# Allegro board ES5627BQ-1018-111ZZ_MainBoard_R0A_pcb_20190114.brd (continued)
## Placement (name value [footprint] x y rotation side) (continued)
CB740  1uF/16V  [CC0402_22X22_8OCT]  25.22 99.67 0 bottom
CB741  1uF/16V  [CC0402_22X22_8OCT]  27.28 99.67 180 bottom
CB742  1uF/16V  [CC0402_22X22_8OCT]  29.21 99.67 0 bottom
CB743  1uF/16V  [CC0402_22X22_8OCT]  31.22 99.67 180 bottom
CB744  1uF/16V  [CC0402_22X22_8OCT]  36.17 99.67 0 bottom
CB745  1uF/16V  [CC0402_22X22_8OCT]  39.17 99.67 180 bottom
CB746  1uF/16V  [CC0402_22X22_8OCT]  41.15 99.67 0 bottom
CB747  1uF/16V  [CC0402_22X22_8OCT]  43.18 99.67 180 bottom
CB748  1uF/16V  [CC0402_22X22_8OCT]  45.14 99.67 0 bottom
CB749  1uF/16V  [CC0402_22X22_8OCT]  47.12 99.67 180 bottom
CB750  1uF/16V  [CC0402_22X22_8OCT]  51.13 99.67 180 bottom
CB751  1uF/16V  [CC0402_22X22_8OCT]  55.12 99.67 180 bottom
CB752  1uF/16V  [CC0402_22X22_8OCT]  49.18 99.63 0 bottom
CB756  1uF/16V  [CC0402_22X22_8OCT]  23.75 99.16 90 bottom
CB757  0.1uF/16V  [CC0402]  111.85 99.16 270 bottom
CB758  1uF/16V  [CC0402_22X22_8OCT]  56.71 99.13 90 bottom
CB759  10uF/16V  [CC0805]  196.39 102.56 90 top
CB765  1uF/16V  [CC0402_22X22_8OCT]  21.21 98.66 0 bottom
CB766  1uF/16V  [CC0402_22X22_8OCT]  53.21 98.63 0 bottom
CB767  1uF/16V  [CC0402_22X22_8OCT]  27.18 97.64 0 bottom
CB768  1uF/16V  [CC0402_22X22_8OCT]  31.17 97.64 0 bottom
CB769  1uF/16V  [CC0402_22X22_8OCT]  35.18 97.64 0 bottom
CB770  1uF/16V  [CC0402_22X22_8OCT]  39.17 97.64 0 bottom
CB771  1uF/16V  [CC0402_22X22_8OCT]  43.21 97.64 0 bottom
CB772  1uF/16V  [CC0402_22X22_8OCT]  47.22 97.64 0 bottom
CB773  1uF/16V  [CC0402_22X22_8OCT]  51.21 97.64 0 bottom
CB774  1uF/16V  [CC0402_22X22_8OCT]  55.25 97.64 0 bottom
CB775  1uF/16V  [CC0402_22X22_8OCT]  23.75 97.15 90 bottom
CB776  1nF  [CC0402]  113.5 97.13 180 bottom
CB783  470uF/2V/4A  [CAP_6D4_2SP_4D3W7D3L2D1H]  82.39 95.86 0 bottom
CB786  100uF/6.3V  [CC1206]  154.78 84.94 270 top
CB787  100uF/6.3V  [CC1206]  163.73 93.11 0 bottom
CB788  100uF/6.3V  [CC1206]  166.01 93.11 0 bottom
CB789  100uF/6.3V  [CC1206]  168.42 93.11 0 bottom
CB790  0.1uF  [CC0603]  145.73 99.55 270 bottom
CB793  100uF/6.3V  [CC1206]  154.73 87.4 90 bottom
CB796  0.1uF/16V  [CC0402]  180.13 68.74 0 top
CB797  22uF, 16V  [CC1206]  237.63 70.05 180 bottom
CB799  0.1uF/16V  [CC0402]  35.33 68.74 0 top
CB800  0.1uF/16V  [CC0402]  41.36 68.87 180 bottom
CB801  0.1uF/16V  [CC0402]  60.41 68.74 0 top
CB806  0.1uF/16V  [CC0402]  72.92 68.74 180 bottom
CB807  0.1uF/16V  [CC0402]  72.92 68.74 0 top
CB808  0.1uF/16V  [CC0402]  85.44 68.68 180 bottom
CB809  0.1uF/16V  [CC0402]  85.44 68.68 0 top
CB810  0.1uF/16V  [CC0402]  109.77 68.87 180 bottom
CB811  0.1uF/16V  [CC0402]  116.25 68.74 180 bottom
CB812  0.1uF/16V  [CC0402]  128.82 68.74 0 top
CB813  0.1uF/16V  [CC0402]  122.35 68.87 0 top
CB814  0.1uF/16V  [CC0402]  136.96 68.62 180 bottom
CB815  0.1uF/16V  [CC0402]  136.96 68.62 0 top
CB816  0.1uF/16V  [CC0402]  154.98 68.74 0 top
CB817  0.1uF/16V  [CC0402]  154.98 68.74 180 bottom
CB818  0.1uF/16V  [CC0402]  161.02 68.87 0 top
CB819  0.1uF/16V  [CC0402]  167.49 68.74 180 bottom
CB820  0.1uF/16V  [CC0402]  173.65 68.87 180 bottom
CB821  0.1uF/16V  [CC0402]  186.29 68.87 0 top
CB822  0.1uF/16V  [CC0402]  192.77 68.74 0 top
CB827  0.1uF/16V  [CC0402]  35.33 68.74 180 bottom
CB828  0.1uF/16V  [CC0402]  41.36 68.87 0 top
CB829  0.1uF/16V  [CC0402]  60.41 68.74 180 bottom
CB832  22uF/6.3V  [CC0603]  67.46 66.4 270 top
CB833  22uF/6.3V  [CC0603]  71.78 66.39 270 bottom
CB834  22uF/6.3V  [CC0603]  79.97 66.39 270 top
CB835  22uF/6.3V  [CC0603]  84.23 66.4 270 bottom
CB836  22uF/6.3V  [CC0603]  110.79 66.39 270 top
CB837  22uF/6.3V  [CC0603]  115.11 66.39 270 bottom
CB838  22uF/6.3V  [CC0603]  123.36 66.39 270 top
CB839  22uF/6.3V  [CC0603]  127.68 66.39 270 bottom
CB840  22uF/6.3V  [CC0603]  131.63 66.27 270 top
CB841  22uF/6.3V  [CC0603]  135.82 66.27 270 bottom
CB842  22uF/6.3V  [CC0603]  149.52 66.4 270 top
CB843  22uF/6.3V  [CC0603]  153.84 66.39 270 bottom
CB844  22uF/6.3V  [CC0603]  161.91 66.4 270 top
CB845  22uF/6.3V  [CC0603]  166.35 66.4 270 bottom
CB846  22uF/6.3V  [CC0603]  174.67 66.39 270 top
CB847  22uF/6.3V  [CC0603]  178.99 66.39 270 bottom
CB848  22uF/6.3V  [CC0603]  187.31 66.39 270 top
CB849  22uF/6.3V  [CC0603]  191.62 66.39 270 bottom
CB852  22uF/6.3V  [CC0603]  29.87 66.39 270 top
CB853  22uF/6.3V  [CC0603]  34.19 66.39 270 bottom
CB854  22uF/6.3V  [CC0603]  42.32 66.4 270 top
CB855  22uF/6.3V  [CC0603]  46.7 66.39 90 top
CB856  22uF/6.3V  [CC0603]  59.27 66.39 90 top
CB857  22uF/6.3V  [CC0603]  54.95 66.4 270 top
CB858  0.1uF/16V  [CC0402]  29.36 65.12 270 top
CB859  0.1uF/16V  [CC0402]  34.7 65.12 270 bottom
CB860  0.1uF/16V  [CC0402]  41.93 65.06 270 top
CB861  0.1uF/16V  [CC0402]  47.2 65.12 90 top
CB862  0.1uF/16V  [CC0402]  59.78 65.12 90 top
CB863  0.1uF/16V  [CC0402]  54.51 65.13 270 top
CB864  0.1uF/16V  [CC0402]  67.08 65.13 270 top
CB865  0.1uF/16V  [CC0402]  72.29 65.12 270 bottom
CB866  0.1uF/16V  [CC0402]  79.46 65.12 270 top
CB867  0.1uF/16V  [CC0402]  84.73 65.13 270 bottom
CB868  0.1uF/16V  [CC0402]  110.28 65.12 270 top
CB869  0.1uF/16V  [CC0402]  115.61 65.12 270 bottom
CB870  0.1uF/16V  [CC0402]  122.85 65.12 270 top
CB871  0.1uF/16V  [CC0402]  128.19 65.12 270 bottom
CB872  0.1uF/16V  [CC0402]  130.99 65 270 top
CB873  0.1uF/16V  [CC0402]  136.33 65 270 bottom
CB874  0.1uF/16V  [CC0402]  149.02 65.13 270 top
CB875  0.1uF/16V  [CC0402]  154.35 65.12 270 bottom
CB876  0.1uF/16V  [CC0402]  161.52 65.13 270 top
CB877  0.1uF/16V  [CC0402]  166.83 65.12 270 bottom
CB878  0.1uF/16V  [CC0402]  174.16 65.12 270 top
CB879  0.1uF/16V  [CC0402]  179.5 65.12 270 bottom
CB880  0.1uF/16V  [CC0402]  186.8 65.12 270 top
CB881  0.1uF/16V  [CC0402]  192.13 65.12 270 bottom
CB883  0.1uF/16V  [CC0402]  179.59 21.46 90 bottom
CB892  10uF/6.3V  [CC0603]  220.07 112.27 90 top
CB893  @1nF  [CC0402]  239.18 80.17 90 top
CB894  @1nF  [CC0402]  241.09 80.17 270 top
CB895  @1nF  [CC0402]  242.99 80.17 90 top
CB896  @1nF  [CC0402]  244.9 80.17 90 top
CB898  10uF/6.3V  [CC0603]  220.08 109.34 270 top
CB899  0.1uF/16V  [CC0402]  211.3 75.42 90 top
CB900  0.1uF/16V  [CC0402]  199.55 74.65 90 top
CB901  0.1uF/16V  [CC0402]  207.43 75.42 90 top
CB902  0.1uF/16V  [CC0402]  211.3 75.42 270 bottom
CB903  0.1uF/16V  [CC0402]  240.12 155.93 270 top
CB904  22uF/6.3V  [CC0805]  199.74 76.3 90 top
CB905  22uF/6.3V  [CC0805]  211.81 76.95 270 bottom
CB906  22uF/6.3V  [CC0805]  208 76.95 90 top
CB907  22uF/6.3V  [CC0805]  211.81 76.95 90 top
CB908  0.1uF/16V  [CC0402]  216.25 75.28 90 top
CB909  0.1uF/16V  [CC0402]  204.44 75.35 270 top
CB910  22uF/6.3V  [CC0805]  204.05 76.93 270 top
CB911  22uF/6.3V  [CC0805]  215.61 76.93 90 top
CB912  @100pF/100V  [CC0402]  244.44 153.77 0 top
CB913  @100pF/100V  [CC0402]  244.44 155.67 180 top
CB914  0.1uF/16V  [CC0402]  244.06 157.71 90 top
CB915  @100pF/100V  [CC0402]  247.49 152.5 180 top
CB916  @100pF/100V  [CC0402]  247.49 150.59 0 top
CB917  22uF/6.3V  [CC0805]  206.8 84.25 180 top
CB918  22uF/6.3V  [CC0805]  213.63 84.27 180 top
CB919  0.1uF/16V  [CC0402]  202.34 79.35 0 top
CB920  0.1uF/16V  [CC0402]  215.36 83.16 180 top
CB921  0.1uF/16V  [CC0402]  242.15 157.71 90 top
CB922  0.1uF/16V  [CC0402]  246.98 157.71 270 top
CB923  0.1uF/16V  [CC0402]  242.92 152.37 90 top
CB926  @100pF/100V  [CC0402]  256.94 35.18 0 bottom
CB927  @100pF/100V  [CC0402]  260.79 35.18 0 bottom
CB928  @100pF/100V  [CC0402]  256.94 35.18 180 top
CB929  @100pF/100V  [CC0402]  260.79 35.18 180 top
CB930  @100pF/100V  [CC0402]  258.74 35.18 0 bottom
CB931  @100pF/100V  [CC0402]  258.74 35.18 180 top
CB937  0.1uF/16V  [CC0402]  249.65 67.79 180 bottom
CB938  @0.1uF/16V  [CC0402]  88.89 29.47 270 bottom
CB942  0.1uF  [CC0402]  243.36 8.93 180 bottom
CB949  0.1uF/16V  [CC0402]  136.87 21.56 90 bottom
CB950  0.1uF  [CC0402]  242.34 8.93 180 bottom
CB951  0.1uF/16V  [CC0402]  63.54 21.46 90 bottom
CB952  0.1uF/16V  [CC0402]  101.03 25.87 90 bottom
CB953  0.1uF  [CC0402]  248.69 8.93 180 bottom
CB954  0.1uF  [CC0402]  247.68 8.93 180 bottom
CB956  10uF/16V  [CC0805]  103.95 24.47 90 bottom
CB957  0.1uF/16V  [CC0402]  106.36 24.47 0 bottom
CB958  @47pF/50V  [CC0402]  88.89 19.31 270 bottom
CB959  @47pF/50V  [CC0402]  90.8 19.31 270 bottom
CB962  0.1uF/16V  [CC0402]  101.15 21.93 180 bottom
CB972  100uF/6.3V  [CAP_6D2_2SP_4D3W7D3L2D1H]  104.46 17.99 270 bottom
CB973  0.1uF/16V  [CC0402]  83.28 206.09 0 top
CB974  22uF/16V  [CC1206]  100.9 17.48 180 bottom
CB975  0.1uF/16V  [CC0402]  158.72 239.49 270 top
CB976  0.1uF  [CC0402]  123.54 208.7 270 top
CB977  0.1uF  [CC0402]  48.42 10.83 180 bottom
CB978  0.1uF  [CC0402]  123.49 218.89 270 top
CB979  0.1uF  [CC0402]  61.31 10.83 180 bottom
CB980  0.1uF  [CC0402]  98.01 236.38 180 top
CB981  0.1uF  [CC0402]  34.83 10.83 180 bottom
CB982  0.1uF  [CC0402]  44.35 10.83 180 bottom
CB983  0.1uF  [CC0402]  46.39 10.83 180 bottom
CB984  0.1uF  [CC0402]  63.34 10.83 180 bottom
CB985  0.1uF/16V  [CC0402]  179.59 7.72 90 bottom
CB986  100uF /6.3V  [CC1206]  103.55 100.81 180 bottom
CB987  100uF /6.3V  [CC1206]  101.26 100.81 180 bottom
CB994  10nF/50V  [CC0402_22X22_8OCT]  230.68 117.65 0 bottom
CB995  2.2uF/6.3V  [CC0603]  220.07 113.73 270 top
CB996  0.1uF/16V  [CC0402_22X22_8OCT]  231.68 118.65 0 bottom
CB997  0.1uF/16V  [CC0402_22X22_8OCT]  227.68 118.65 0 bottom
CB998  0.1uF/16V  [CC0402_22X22_8OCT]  231.18 128.15 90 bottom
CB999  10uF/6.3V  [CC0603]  219.99 130.07 90 top
CB1000  10uF/6.3V  [CC0603]  220.05 134.54 270 top
CB1001  10nF/50V  [CC0402_22X22_8OCT]  228.18 126.15 270 bottom
CB1002  2.2uF/6.3V  [CC0603]  220 131.54 270 top
CB1003  0.1uF/16V  [CC0402_22X22_8OCT]  228.18 125.15 270 bottom
CB1004  0.1uF/16V  [CC0402_22X22_8OCT]  228.18 124.15 270 bottom
CB1005  0.1uF/16V  [CC0402_22X22_8OCT]  231.18 121.15 90 bottom
CB1006  0.1uF/16V  [CC0402_22X22_8OCT]  227.68 120.65 180 bottom
CB1007  0.1uF/16V  [CC0402_22X22_8OCT]  232.18 127.15 90 bottom
CB1008  0.1uF/16V  [CC0402_22X22_8OCT]  230.18 127.15 90 bottom
CB1010  0.1uF/16V  [CC0402_22X22_8OCT]  229.68 118.65 0 bottom
CB1011  10uF/6.3V  [CC0603]  239.29 133.43 270 top
CB1012  10uF/6.3V  [CC0603]  239.3 136.39 90 top
CB1013  10nF/50V  [CC0402_22X22_8OCT]  231.18 120.15 90 bottom
CB1014  2.2uF/6.3V  [CC0603]  239.3 131.99 90 top
CB1015  0.1uF/16V  [CC0402_22X22_8OCT]  232.68 120.65 0 bottom
CB1016  0.1uF/16V  [CC0402_22X22_8OCT]  231.18 124.15 90 bottom
CB1017  0.1uF/16V  [CC0402_22X22_8OCT]  228.68 118.65 0 bottom
CB1018  0.1uF/16V  [CC0402_22X22_8OCT]  232.18 125.15 90 bottom
CB1019  10uF/6.3V  [CC0603]  220 128.62 270 top
CB1020  10nF/50V  [CC0402_22X22_8OCT]  228.68 127.65 180 bottom
CB1021  10uF/6.3V  [CC0603]  216.54 128.76 270 top
CB1022  0.1uF/16V  [CC0402_22X22_8OCT]  225.68 121.65 0 bottom
CB1023  2.2uF/6.3V  [CC0603]  220 127.16 90 top
CB1024  0.1uF/16V  [CC0402_22X22_8OCT]  227.18 127.15 270 bottom
CB1025  10uF/6.3V  [CC0603]  220.03 124.17 90 top
CB1026  10nF/50V  [CC0402_22X22_8OCT]  225.68 119.65 0 bottom
CB1027  10uF/6.3V  [CC0603]  216.45 125.67 90 top
CB1028  0.1uF/16V  [CC0402_22X22_8OCT]  234.18 120.15 270 bottom
CB1029  2.2uF/6.3V  [CC0603]  220.03 122.71 270 top
CB1030  0.1uF/16V  [CC0402_22X22_8OCT]  226.68 119.65 0 bottom
CB1031  0.1uF/16V  [CC0402_22X22_8OCT]  234.18 128.15 270 bottom
CB1032  0.1uF/16V  [CC0402_22X22_8OCT]  227.18 128.15 90 bottom
CB1033  0.1uF/16V  [CC0402_22X22_8OCT]  232.18 126.15 90 bottom
CB1034  0.1uF/16V  [CC0402_22X22_8OCT]  232.68 118.65 0 bottom
CB1035  10uF/6.3V  [CC0603]  197.96 216.88 270 top
CB1036  10uF/6.3V  [CC0603]  173.25 174.62 180 top
CB1037  10nF/50V  [CC0402]  184.15 221 0 bottom
CB1038  2.2uF/6.3V  [CC0603]  197.96 218.34 90 top
CB1039  0.1uF/16V  [CC0402]  185.17 221.01 0 bottom
CB1040  0.1uF/16V  [CC0402]  184.18 231.87 180 bottom
CB1041  0.1uF/16V  [CC0402]  191.23 229.64 180 bottom
CB1042  0.1uF/16V  [CC0402]  185.19 231.87 180 bottom
CB1043  0.1uF/16V  [CC0402]  194.28 218.79 180 bottom
CB1044  0.1uF/16V  [CC0402]  192.18 229.32 180 bottom
CB1045  0.1uF/16V  [CC0402]  195.29 218.79 180 bottom
CB1046  10uF/6.3V  [CC0603]  195.43 213.72 180 top
CB1047  10uF/6.3V  [CC0603]  198.41 213.72 0 top
CB1048  10nF/50V  [CC0402]  192.62 232.64 270 bottom
CB1049  2.2uF/6.3V  [CC0603]  193.97 213.72 0 top
CB1050  0.1uF/16V  [CC0402]  192.67 216.13 180 bottom
CB1051  0.1uF/16V  [CC0402]  188.88 230.15 270 bottom
CB1052  0.1uF/16V  [CC0402]  192.62 231.62 270 bottom
CB1053  0.1uF/16V  [CC0402]  188.75 231.54 270 bottom
CB1054  0.1uF/16V  [CC0402]  191.63 216.16 180 bottom
CB1057  0.1uF/16V  [CC0402]  199.68 213.35 180 top
CB1058  0.1uF/16V  [CC0402]  199.99 217.89 180 bottom
CB1059  0.1uF/16V  [CC0402_22X22_8OCT]  39.2 115.65 180 bottom
CB1060  0.1uF/16V  [CC0402_22X22_8OCT]  40.2 115.65 180 bottom
CB1061  0.1uF/16V  [CC0402_22X22_8OCT]  26.7 115.15 90 bottom
CB1062  0.1uF/16V  [CC0402_22X22_8OCT]  26.7 116.15 90 bottom
CB1063  10uF/6.3V  [CC0603]  199.74 223.03 270 top
CB1064  10uF/6.3V  [CC0603]  204.12 223.81 180 bottom
CB1065  2.2uF/6.3V  [CC0603]  199.74 224.5 90 top
CB1066  0.1uF/16V  [CC0402]  202.78 223.62 0 bottom
CB1067  10nF/50V  [CC0402]  191.67 224.81 90 bottom
CB1068  0.1uF/16V  [CC0402]  191.67 223.8 90 bottom
CB1069  10uF/6.3V  [CC0603]  199.74 219.8 270 top
CB1070  10uF/6.3V  [CC0603]  204.12 220.32 0 bottom
CB1071  2.2uF/6.3V  [CC0603]  199.74 221.26 90 top
CB1072  0.1uF/16V  [CC0402]  202.85 220.51 180 bottom
CB1073  10nF/50V  [CC0402]  193.77 221.33 180 bottom
CB1074  0.1uF/16V  [CC0402]  192.24 221.4 180 bottom
CB1075  10uF/6.3V  [CC0603]  199.74 227.67 270 top
CB1076  10uF/6.3V  [CC0603]  202.02 228.45 180 bottom
CB1077  2.2uF/6.3V  [CC0603]  199.74 226.21 90 top
CB1078  0.1uF/16V  [CC0402]  203.29 228.95 0 bottom
CB1079  10nF/50V  [CC0402]  191.1 227.23 0 bottom
CB1080  0.1uF/16V  [CC0402]  196.05 226.46 180 bottom
CB1081  0.1uF/16V  [CC0402]  191.67 225.83 90 bottom
CB1082  0.1uF/16V  [CC0402]  192.12 227.35 0 bottom
CB1083  0.1uF  [CC0402]  246.33 98.83 270 top
CB1084  0.1uF  [CC0402]  236.57 156.31 180 top
CB1085  15pF  [CC0402]  246.32 97.79 270 top
CB1086  15pF  [CC0402]  237.58 156.31 180 top
CB1087  @0.1uF  [CC0402]  239.23 159.36 270 bottom
CB1088  @0.1uF  [CC0402]  234.53 160.37 90 top
CB1089  @0.1uF  [CC0402]  241.93 96.21 0 bottom
CB1090  @0.1uF  [CC0402]  246.33 96.73 270 top
CB1091  0.1uF/16V  [CC0402]  49.94 222.86 0 bottom
CB1094  0.1uF/16V  [CC0402]  14.38 53.73 180 bottom
CB1095  22uF/6.3V  [CC0805]  15.94 53.36 180 bottom
CB1096  0.1uF/16V  [CC0402]  10.95 43.15 90 bottom
CB1097  22uF/6.3V  [CC0805]  10.63 44.74 90 bottom
CB1098  0.1uF/16V  [CC0402]  13.8 49.43 270 bottom
CB1099  22uF/6.3V  [CC0805]  14.68 47.91 270 bottom
CB1100  0.1uF/16V  [CC0402]  10.91 55.53 90 bottom
CB1101  22uF/6.3V  [CC0805]  11.93 53.1 270 bottom
CB1102  22uF/16V  [CC1206]  181.76 149.36 90 bottom
CB1103  @1nF  [CC0402]  225.37 36.41 90 bottom
CB1104  @1nF  [CC0402]  227.27 36.42 90 bottom
CB1105  @1nF  [CC0402]  227.27 36.42 270 top
CB1106  @1nF  [CC0402]  225.36 36.42 90 top
CB1107  0.1uF/16V  [CC0402]  237.33 74.39 90 bottom
CB1108  @1nF  [CC0402]  211.86 14.42 0 bottom
CB1109  @1nF  [CC0402]  211.86 12.54 0 bottom
CB1110  @1nF  [CC0402]  211.85 22.91 180 bottom
CB1111  @1nF  [CC0402]  211.85 21.01 0 bottom
CB1112  1uF  [CC0402]  103.66 220.19 270 bottom
CB1113  1uF  [CC0402]  105.12 216.7 0 bottom
CB1114  1uF  [CC0402]  105.5 218.6 0 bottom
CB1115  0.1uF  [CC0402_22X22_8OCT]  110.75 225.48 0 bottom
CB1116  0.1uF  [CC0402_22X22_8OCT]  110.3 218.94 270 bottom
CB1117  0.1uF  [CC0402_22X22_8OCT]  108.27 214.93 270 bottom
CB1118  0.1uF  [CC0402_22X22_8OCT]  99.28 214.98 90 bottom
CB1119  0.1uF  [CC0402_22X22_8OCT]  100.87 221.46 180 bottom
CB1120  10uF  [CC0402]  84.36 235.87 90 bottom
CB1121  0.1uF  [CC0201]  108.3 212.95 90 bottom
CB1122  0.1uF  [CC0201]  105.71 212.46 0 bottom
CB1123  0.1uF  [CC0201]  112.33 226.97 90 bottom
CB1124  0.1uF  [CC0201]  99.78 211.47 0 bottom
CB1125  0.1uF  [CC0402_22X22_8OCT]  102.3 213.97 270 bottom
CB1126  0.1uF  [CC0402_22X22_8OCT]  105.53 214.6 180 bottom
CB1127  0.1uF  [CC0402_22X22_8OCT]  108.27 213.89 270 bottom
CB1128  0.1uF  [CC0402_22X22_8OCT]  100.8 218.48 0 bottom
CB1129  0.1uF  [CC0402_22X22_8OCT]  102.3 215 270 bottom
CB1130  0.1uF  [CC0402_22X22_8OCT]  107.24 224.95 270 bottom
CB1131  0.1uF  [CC0402_22X22_8OCT]  108.27 227 90 bottom
CB1132  0.1uF  [CC0402_22X22_8OCT]  110.26 220.83 90 bottom
CB1133  0.1uF  [CC0402_22X22_8OCT]  108.34 220.84 270 bottom
CB1134  0.1uF  [CC0402_22X22_8OCT]  105.29 221.98 90 bottom
CB1135  0.1uF  [CC0402_22X22_8OCT]  102.73 225.46 180 bottom
CB1136  10uF  [CC0603]  75.17 218.62 90 bottom
CB1137  0.1uF  [CC0402]  75.3 215.14 90 bottom
CB1138  0.1uF  [CC0402]  75.33 224.96 90 bottom
CB1139  10uF  [CC0402]  84.9 225.35 90 bottom
CB1140  0.1uF  [CC0201]  98.79 212.47 180 bottom
CB1141  0.1uF  [CC0201]  109.8 213.47 0 bottom
CB1142  0.1uF  [CC0201]  103.79 212.44 0 bottom
CB1143  0.1uF  [CC0201]  98.79 228.47 0 bottom
CB1144  0.1uF  [CC0201]  112.26 228.95 270 bottom
CB1145  0.1uF  [CC0201]  112.29 212.96 270 bottom
CB1146  0.1uF  [CC0201]  110.79 212.43 0 bottom
CB1147  10uF  [CC0402]  105.57 208.04 90 bottom
CB1148  0.1uF  [CC0201]  111.78 211.47 0 bottom
CB1149  0.1uF  [CC0201]  106.45 210.92 90 bottom
CB1150  0.1uF  [CC0201]  103.75 210.73 180 bottom
CB1151  0.1uF  [CC0201]  109.8 211.46 0 bottom
CB1152  10uF  [CC0402]  87.91 205.33 180 bottom
CB1153  0.1uF  [CC0201]  112.79 211.47 180 bottom
CB1154  0.1uF  [CC0201]  108.73 210.76 180 bottom
CB1155  0.1uF  [CC0201]  101.78 211.44 180 bottom
CB1156  0.1uF  [CC0201]  100.89 210.6 180 bottom
CB1157  0.1uF  [CC0201]  97.82 226.48 0 bottom
CB1158  0.1uF  [CC0201]  111.28 215.94 270 bottom
CB1159  0.1uF  [CC0201]  111.31 216.96 270 bottom
CB1160  0.1uF  [CC0201]  112.31 218.96 270 bottom
CB1161  0.1uF  [CC0201]  112.31 223.94 270 bottom
CB1162  0.1uF  [CC0201]  108.32 229.28 0 bottom
CB1163  0.1uF  [CC0201]  112.32 220.45 180 bottom
CB1164  0.1uF  [CC0201]  100.26 212.96 270 bottom
CB1165  0.1uF  [CC0201]  112.26 224.95 270 bottom
CB1166  0.1uF  [CC0201]  107.28 227.94 270 bottom
CB1167  0.1uF  [CC0201]  101.27 227.94 90 bottom
CB1168  0.1uF  [CC0201]  101.57 226.92 90 bottom
CB1169  0.1uF  [CC0201]  98.79 224.47 180 bottom
CB1170  0.1uF  [CC0201]  98.3 222.96 270 bottom
CB1171  0.1uF  [CC0201]  98.27 221.96 270 bottom
CB1172  0.1uF  [CC0201]  98.29 216.95 270 bottom
CB1173  0.1uF  [CC0201]  99.31 217.97 270 bottom
CB1174  0.1uF  [CC0201]  98.22 219.97 270 bottom
CB1175  0.1uF  [CC0201]  97.25 217.97 90 bottom
CB1176  0.1uF  [CC0201]  98.25 220.95 270 bottom
CB1177  0.1uF  [CC0201]  111.28 219.97 270 bottom
CB1178  10uF  [CC0402]  84.92 223.82 90 bottom
CB1179  0.1uF  [CC0201]  107.31 221.97 270 bottom
CB1180  0.1uF  [CC0201]  101.82 219.43 0 bottom
CB1188  10uF/6.3V  [CC0603]  143.2 186.43 270 top
CB1195  10uF/6.3V  [CC0603]  161.64 179.11 270 bottom
CB1200  10uF/6.3V  [CC0603]  157.32 186.73 180 top
CB1211  0.1uF/16V  [CC0402]  145.63 171.42 0 bottom
CB1212  10uF/6.3V  [CC0603]  143.73 173.07 90 bottom
CB1217  0.1uF/16V  [CC0402]  43.76 204.1 90 top
CB1218  10uF/6.3V  [CC0603]  43.38 206.39 270 top
CB1221  10uF/6.3V  [CC0603]  110.71 176.63 90 top
CB1224  0.1uF/16V  [CC0402]  142.73 162.26 0 top
CB1227  0.1uF/16V  [CC0402]  143.73 162.26 0 top
CB1228  0.1uF  [CC0402]  73.69 10.83 180 bottom
CB1229  0.1uF  [CC0402]  71.66 10.83 180 bottom
CONN2  LCH24-K0324S11C-12  [CONN_2D54_3SP_4W7D62L9D3H_1]  167.31 258.43 180 top
CONN3  @VDD0P6_PG  [CONN_1DP_2D54WL8D94H_PIP]  58.19 190.16 90 top
CONN5  LCB25-G2024S01C-04  [CONNM_1D27X4D05_2X10SP_27D2W]  9.24 233.71 90 top
CONN6  MINI-FIT  [CONN_4D2X5D5_12X2DP_52W_PIP]  47.87 230.69 0 top
CONN8  @VDD0P6  [CONN_1DP_2D54WL8D94H_PIP]  37.23 173.56 0 top
CONN9  @LM75BD3_INT  [CONN_1DP_2D54WL8D94H_PIP]  2.73 175.35 0 top
CONN10  @VDD1P8  [CONN_1DP_2D54WL8D94H_PIP]  79.21 151.36 0 top
CONN13  @VCC3V3_PG  [CONN_1DP_2D54WL8D94H_PIP]  173.64 129.64 270 top
CONN16  @VDD1P8_PG  [CONN_1DP_2D54WL8D94H_PIP]  111.25 140.79 270 top
CONN18  @LM75BD2_INT  [CONN_1DP_2D54WL8D94H_PIP]  132.68 202.54 90 top
CONN19  @LM75BD1_INT  [CONN_1DP_2D54WL8D94H_PIP]  139.03 222.73 90 bottom
CONN23  @VDD1P2_DDR  [CONN_1DP_2D54WL8D94H_PIP]  128.45 159.05 180 top
CONN24  @VCC5P0  [CONN_1DP_2D54WL8D94H_PIP]  236.82 168.37 270 bottom
CONN26  @OCXO_Vout  [CONN_1DP_2D54WL8D94H_PIP]  256.51 144.4 270 top
CONN28  LCH25-K1024S01C-13  [CONNM_2D54X4D65_2X5SP_12D7W5L]  262.25 224.01 270 top
CONN29  @VDD1P0_ROV  [CONN_1DP_2D54WL8D94H_PIP]  95.98 123.92 180 top
CONN31  @VPP_DDR2P5_PG  [CONN_1DP_2D54WL8D94H_PIP]  50.57 195.11 90 top
CONN32  @VDD3P3  [CONN_1DP_2D54WL8D94H_PIP]  143.73 134.08 270 top
CONN34  @VDD1P2_DDR_PG  [CONN_1DP_2D54WL8D94H_PIP]  131.85 167.61 180 top
CONN35  @VPP_DDR2P5  [CONN_1DP_2D54WL8D94H_PIP]  46.19 173.14 90 top
CONN36  @AP7362_ADJ  [CONN_1DP_2D54WL8D94H_PIP]  263.97 140.01 180 top
CONN40  @VDD1P0  [CONN_1DP_2D54WL8D94H_PIP]  105.78 111.91 0 top
CONN41  BHE6T0-210S4  [CONN_2D54X6D9_2X5SP_20D32W8D8L]  35.57 254.31 0 top
CONN43  @VDD1P25_PG  [CONN_1DP_2D54WL8D94H_PIP]  90.39 104.24 0 top
CONN44  TMM-104-01-T-D-SM-P-TR  [CONNM_2DX4D27_2X4SP_3D937W]  211.16 95.05 270 top
CONN45  @VDD1P25  [CONN_1DP_2D54WL8D94H_PIP]  101.31 95.04 0 top
CONN46  @VCC1V_PG  [CONN_1DP_2D54WL8D94H_PIP]  121.31 95.06 0 top
CONN47  @XFP_3V3_PG  [CONN_1DP_2D54WL8D94H_PIP]  149.88 111.12 0 top
CONN48  @XFP_3V3  [CONN_1DP_2D54WL8D94H_PIP]  149.68 103.99 0 top
CONN52  @MANG_2P5  [CONN_1DP_2D54WL8D94H_PIP]  211.23 119.6 270 top
CONN53_PF  QSFP_FEMALE_2X1P_FIT99_G23  [QSFP_2X1X38DP_19D5W73D3L]  200.09 53.58 0 top
CONN54_PF  SFP_FEMALE_2X6P_FIT293_G53  [MT_RJS_2X6X20DP_86D35W63D25L_PF]  27.31 47.1 0 top
CONN55_PF  SFP_FEMALE_2X6P_FIT293_G53  [MT_RJS_2X6X20DP_86D35W63D25L_PF]  114.86 47.1 0 top
CONN56  5-104655-4  [CONN_1D27X4D62_2X15SP_22D14W]  238.45 252.07 180 top
CONN57  LCH25-K1024S01C-13  [CONNM_2D54X4D65_2X5SP_12D7W5L]  56.42 213.77 90 top
CONN58  LCH25-K1024S01C-13  [CONNM_2D54X4D65_2X5SP_12D7W5L]  262.31 205.26 90 top
CONNB2  2USAB-041T-12H  [USB_2D5_4SP_14D8W14L]  89.23 10.6 180 bottom
D1  SS1040  [SOD123_3D28_2SP_AC]  249.71 194.56 90 top
D2  @SS1040  [SOD123_3D28_2SP_AC]  258.42 164.69 270 bottom
D3  BAT54WS  [SOD323_2D3_2SP_1D85W1D25L]  166.87 121.38 90 top
D4  BAT54WS  [SOD323_2D3_2SP_1D85W1D25L]  165.25 106.96 180 top
D5  BAT54WS  [SOD323_2D3_2SP_1D85W1D25L]  154.02 105.89 180 top
D6  SIDACTOR  [DO214AA_4D_2SP_3D625W5D35L2D65H]  250.88 43.48 270 top
D7  SIDACTOR  [DO214AA_4D_2SP_3D625W5D35L2D65H]  255.01 43.48 270 top
D9  BAT54C-7-F  [SOT23_3SP_A1_A2_C]  213.89 249.31 0 top
D10  BAW56  [SOT23_D95X2D_3SP_1D3W2D9L_C1C2A]  158.52 255.18 0 top
DB1  SIDACTOR  [DO214AA_4D_2SP_3D625W5D35L2D65H]  255.01 43.48 270 bottom
DB2  SIDACTOR  [DO214AA_4D_2SP_3D625W5D35L2D65H]  250.88 43.48 270 bottom
DB7  SS1040  [SOD123_3D28_2SP_AC]  82.39 203.75 90 top
F1  10A  [FUSE_5D8_2SP_6D1W2D49L]  243.42 34.81 90 top
F2  10A  [FUSE_5D8_2SP_6D1W2D49L]  239.84 34.81 90 top
F3  10A  [FUSE_5D8_2SP_6D1W2D49L]  239.87 34.83 90 bottom
F4  10A  [FUSE_5D8_2SP_6D1W2D49L]  243.45 34.78 90 bottom
F5  10A  [FUSE_5D8_2SP_6D1W2D49L]  250.78 34.81 90 top
F6  10A  [FUSE_5D8_2SP_6D1W2D49L]  254.46 34.81 90 top
FB1  @10A  [FUSE_5D8_2SP_6D1W2D49L]  216.44 206.46 180 bottom
FB2  10A  [FUSE_5D8_2SP_6D1W2D49L]  216.47 202.48 180 bottom
FB4  10A  [FUSE_5D8_2SP_6D1W2D49L]  254.46 34.81 90 bottom
FB5  10A  [FUSE_5D8_2SP_6D1W2D49L]  250.77 34.81 90 bottom
FB12  @10A  [FUSE_5D8_2SP_6D1W2D49L]  180.49 152.91 0 bottom
FB17  10A  [FUSE_5D8_2SP_6D1W2D49L]  192.5 123.1 90 top
H1  SCREW_8_2  [MTH_276C138D_8DP_OSP]  5.87 182.28 0 top
H2  SCREW_8_2  [MTH_276C138D_8DP_OSP]  144.65 258.7 0 top
H3  SCREW_8_2  [MTH_276C138D_8DP_OSP]  264.65 258.7 0 top
H4  SCREW_8_2  [MTH_276C138D_8DP_OSP_6OCT]  191.36 163.2 0 top
H5  SCREW_8_2  [MTH_276C138D_8DP_OSP]  91.46 145.41 0 top
H6  SCREW_8_2  [MTH_276C138D_8DP_OSP]  7.2 256.7 0 top
H7  SCREW_8_2  [MTH_276C138D_8DP_OSP_6OCT]  216.84 227.5 0 top
H8  SCREW_8_2  [MTH_276C138D_8DP_OSP]  264.65 98.7 0 top
H10  SCREW_8_2  [MTH_276C138D_8DP_OSP_6OCT]  246.84 227.5 0 top
H11  SCREW_8_2  [MTH_276C138D_8DP_OSP]  30.3 216.7 0 top
H12  SCREW_8_2  [MTH_276C138D_8DP_OSP_6OCT]  163.36 207.2 0 top
H14  SCREW_8_2  [MTH_276C118D_8DP_OSP]  7.2 72.2 90 top
H15  SCREW_8_2  [MTH_276C138D_8DP_OSP]  98.58 71.61 0 top
H17  SCREW_8_2  [MTH_276C118D_8DP_OSP]  264.95 52.61 0 top
H18  SCREW_8_2  [MTH_276C138D_8DP_OSP_6OCT]  139.67 86.07 0 top
H19  SCREW_8_2  [MTH_276C138D_8DP_OSP_6OCT]  200.12 86.07 0 top
H20  SCREW_8_2  [MTH_276C138D_8DP_OSP]  264.65 178.7 0 top
H21  SCREW_8_2  [MTH_276C138D_8DP_OSP_6OCT]  200.12 112.11 0 top
H22  SCREW_8_2  [MTH_276C138D_8DP_OSP_6OCT]  139.67 112.11 0 top
H23  SCREW_8_2  [MTH_276C138D_8DP_OSP_6OCT]  129.84 227.5 0 top
H24  SCREW_8_2  [MTH_276C138D_8DP_OSP_6OCT]  246.84 140.5 0 top
H25  SCREW_8_2  [MTH_276C138D_8DP_OSP_6OCT]  205.84 140.5 0 top
H26  SCREW_8_2  [MTH_276C138D_8DP_OSP_6OCT]  129.84 140.5 0 top
HS1  HEATSINK_4PIN  [HSINK_61DX56D9_4DP_74D4W_OSP]  39.17 116.17 270 top
HSB1  Bracket  [BRACKET_56D9X61D_4DPNP_70W65D9L]  39.17 116.17 0 bottom
J1_PF  qsfp28_single_cage  [QSFP28_SINGLE_CAGE]  12.24 30.41 90 top
J2  3-5353652-6  [CONN_D5X5D4X6D6_110X4SP_61D9W]  171.19 148.5 0 top
J3  4CEGT-671-12EM  [CONN_D5X7D55_75SP_7NP_21D9W4D2H]  130.32 249.68 270 top
J4  GS028L-0212-24A  [SOCKET_BATT_14D65_2SP_AC_MEGA_2]  191.87 251.3 90 top
J5  1241150-3  [CONN_2D54X2D54_3SP_2D5W7D62L]  217.53 255.49 180 top
L1  @220ohm 3A 0.05ohm  [LC0603]  170.22 178.19 180 top
L2  220ohm 3A 0.05ohm  [LC0603]  171.73 178.15 180 top
L3  220ohm 3A 0.05ohm  [LC0603]  81.6 211.31 180 top
L4  220ohm 3A 0.05ohm  [LC0603]  181.66 196.93 90 top
L7  100ohm 500mA  [LC0603]  200.18 236.51 270 top
L8  220ohm 3A 0.05ohm  [LC0603]  9.49 164.55 0 top
L9  100MHz/3A  [LC0603]  112.94 134.93 90 top
L10  0.3A/100MHz  [LC0402]  60.54 85.4 180 top
L12  100MHz/3A/0.05ohm  [LC0805]  20.89 146.83 180 top
L13  100MHz/3A/0.05ohm  [LC0805]  23.16 146.82 180 top
L15  100MHz/3A/0.05ohm  [LC0805]  28.9 142.66 90 top
L16  100MHz/5A/0.01ohm  [LC0603]  56.23 141.58 90 top
L17  100MHz/3A/0.05ohm  [LC0805]  38.19 140.56 180 top
L18  100MHz/3A/0.05ohm  [LC0805]  10 135.99 270 top
L19  2.2uH  [IND_6D1_2SP_7D3W7D5L6H_1]  118.48 165.01 270 top
L20  100MHz/3A  [LC0603]  30.2 186.14 180 top
L21  3.3uH/9.5A/22mohm  [IND_6D1_2SP_7D3W7D5L6H_1]  257.47 169.56 90 top
L22  100MHz/3A  [LC0603]  259.43 161.64 90 top
L23  150nH  [IND_7D7_2SP_7D8W10D2L_1]  89.88 129.89 0 top
L24  100MHz 220ohm 25% 3A 0.05ohm  [LC0603]  222.31 148.51 270 bottom
L25  100ohm 500mA  [LC0603]  242.75 125.45 180 top
L26  100MHz /5A  [LC0603]  169.03 122.65 180 top
L27  100MHz /5A  [LC0603]  170.68 122.65 180 top
L28  3.3uH +-20% 7A 19.9mohm  [CHOKE_6D05_2SP_6D6WL5H]  49.06 187.24 180 top
L29  1.5uH  [IND_11D1_2SP_12D5WL6H]  150.23 122.48 180 top
L30  100MHz/5A/0.01ohm  [LC0603]  61.57 121.26 180 top
L31  150nH  [IND_7D7_2SP_7D8W10D2L_1]  89.88 116.94 180 top
L32  100MHz 220ohm 25% 3A 0.05ohm  [LC0603]  243.17 134.08 90 top
L33  100MHz/3A/0.05ohm  [LC0805]  63.34 113.64 90 top
L36  100MHz/3A  [LC0603]  114.39 182.6 270 top
L37  100MHz /5A  [LC0603]  163.98 110.64 180 top
L38  100MHz /5A  [LC0603]  165.5 110.64 180 top
L40  100MHz/3A  [LC0603]  123.28 109.07 180 top
L41  100MHz/3A/0.05ohm  [LC0805]  9.13 108.84 270 top
L42  100MHz/3A/0.05ohm  [LC0805]  9.13 106.55 270 top
L43  1uH  [IND_5D1_2SP_7D1WL4D2H]  105.25 106.02 0 top
L44  100MHz/10A/4m ohm  [LC3312]  72.23 106.02 270 top
L45  100MHz/10A/1m ohm  [LC3312_1]  86.33 103.86 0 top
L46  100MHz/3A/0.05ohm  [LC0805]  11.52 99.92 270 top
L47  100MHz/3A/0.05ohm  [LC0805]  7.46 99.16 90 top
L48  100MHz/3A/0.05ohm  [LC0805]  11.52 97.38 270 top
L49  100ohm 500mA  [LC0603]  213.44 106.02 0 top
L50  100ohm 500mA  [LC0603]  211.1 106.79 270 top
L51  100MHz/10A/1m ohm  [LC3312_1]  82.9 95.86 270 top
L52  100MHz/3A/0.05ohm  [LC0805]  11.52 95.1 270 top
L53  1.5uH  [IND_11D1_2SP_12D5WL6H]  164.27 94.06 270 top
L54  0.3A/100MHz  [LC0402]  9.92 92.89 90 top
L55  100ohm 500mA  [LC0603]  238.93 94.89 90 top
L56  4.7uH  [IND_1D6_2SP_1D6W2L1H]  68.3 68.93 0 bottom
L57  4.7uH  [IND_1D6_2SP_1D6W2L1H]  71.14 68.93 180 top
L58  4.7uH  [IND_1D6_2SP_1D6W2L1H]  80.73 68.93 0 bottom
L59  4.7uH  [IND_1D6_2SP_1D6W2L1H]  83.54 68.93 180 top
L60  4.7uH  [IND_1D6_2SP_1D6W2L1H]  111.55 68.93 0 bottom
L61  4.7uH  [IND_1D6_2SP_1D6W2L1H]  114.47 68.93 180 top
L62  4.7uH  [IND_1D6_2SP_1D6W2L1H]  124.12 68.93 0 bottom
L63  4.7uH  [IND_1D6_2SP_1D6W2L1H]  127.04 68.93 180 top
L64  4.7uH  [IND_1D6_2SP_1D6W2L1H]  132.29 68.81 0 bottom
L65  4.7uH  [IND_1D6_2SP_1D6W2L1H]  135.18 68.81 180 top
L66  4.7uH  [IND_1D6_2SP_1D6W2L1H]  150.32 68.93 0 bottom
L67  4.7uH  [IND_1D6_2SP_1D6W2L1H]  153.21 68.93 180 top
L68  4.7uH  [IND_1D6_2SP_1D6W2L1H]  162.89 68.93 0 bottom
L69  4.7uH  [IND_1D6_2SP_1D6W2L1H]  165.75 68.93 180 top
L70  4.7uH  [IND_1D6_2SP_1D6W2L1H]  175.43 68.93 0 bottom
L71  4.7uH  [IND_1D6_2SP_1D6W2L1H]  178.35 68.93 180 top
L72  4.7uH  [IND_1D6_2SP_1D6W2L1H]  188.07 68.93 0 bottom
L73  4.7uH  [IND_1D6_2SP_1D6W2L1H]  190.99 68.93 180 top
L74  4.7uH  [IND_1D6_2SP_1D6W2L1H]  30.63 68.93 0 bottom
L75  4.7uH  [IND_1D6_2SP_1D6W2L1H]  33.55 68.93 180 top
L76  4.7uH  [IND_1D6_2SP_1D6W2L1H]  43.15 68.93 0 bottom
L77  4.7uH  [IND_1D6_2SP_1D6W2L1H]  46.06 68.93 0 bottom
L78  4.7uH  [IND_1D6_2SP_1D6W2L1H]  55.72 68.93 0 bottom
L79  4.7uH  [IND_1D6_2SP_1D6W2L1H]  58.63 68.93 0 bottom
L91  100MHz/3A  [LC0603]  98.01 103.76 270 top
L92  100MHz /5A  [LC0603]  106.52 114.32 90 top
L93  100MHz /5A  [LC0603]  106.49 115.64 90 top
L94  100MHz/3A  [LC0603]  225.95 135.2 180 top
L95  100MHz/3A/220mohm  [LC0603]  197.96 218.34 90 bottom
L96  100MHz/3A/220mohm  [LC0603]  196.95 213.72 180 top
L97  100MHz/3A/220mohm  [LC0603]  199.74 223.03 90 bottom
L98  100MHz/3A/220mohm  [LC0603]  199.74 221.26 90 bottom
L99  100MHz/3A/220mohm  [LC0603]  199.74 227.67 90 bottom
L101  100ohm 500mA  [LC0603]  234.56 183.14 0 bottom
L102  100ohm 500mA  [LC0603]  232.54 183.14 0 bottom
L103  100MHz/500mA/350mohm.  [LC0603]  161.64 180.57 90 bottom
L105  100MHz/500mA/350mohm.  [LC0603]  150.4 183.51 90 bottom
L106  100MHz/500mA/350mohm.  [LC0603]  149.22 185.91 90 bottom
L107  100MHz/500mA/350mohm.  [LC0603]  150.42 170.66 270 bottom
L108  100MHz/500mA/350mohm.  [LC0603]  153.38 169.57 0 bottom
L109  100MHz/500mA/350mohm.  [LC0603]  146.55 186.83 0 top
LB1  220ohm 3A 0.05ohm  [LC0603]  88.32 183.27 180 top
LB4  220ohm 3A 0.05ohm  [LC0603]  92.96 186.62 180 top
LB5  @220ohm 3A 0.05ohm  [LC0603]  170.21 174.66 0 top
LB6  220ohm 3A 0.05ohm  [LC0603]  171.73 174.66 0 top
LB8  220ohm 3A 0.05ohm  [LC0603]  90.04 194.49 0 top
LB20  100MHz/10A/1m ohm  [LC3312_1]  111.86 164.56 180 bottom
LB21  100MHz/10A/1m ohm  [LC3312_1]  111.98 164.31 180 top
LB22  100MHz/10A/1m ohm  [LC3312_1]  121.12 154.15 0 bottom
LB23  100MHz/10A/1m ohm  [LC3312_1]  81.96 88.19 0 top
LB24  100MHz/10A/1m ohm  [LC3312_1]  104.34 90.9 180 top
LB25  100MHz/10A/1m ohm  [LC3312_1]  107.23 88.72 180 bottom
LB26  100ohm 500mA  [LC0603]  198.02 96.62 90 top
LB30  4.7uH  [IND_1D6_2SP_1D6W2L1H]  68.3 68.93 180 top
LB31  4.7uH  [IND_1D6_2SP_1D6W2L1H]  71.14 68.93 0 bottom
LB32  4.7uH  [IND_1D6_2SP_1D6W2L1H]  80.73 68.93 180 top
LB33  4.7uH  [IND_1D6_2SP_1D6W2L1H]  83.54 68.93 0 bottom
LB34  4.7uH  [IND_1D6_2SP_1D6W2L1H]  111.55 68.93 180 top
LB35  4.7uH  [IND_1D6_2SP_1D6W2L1H]  114.47 68.93 0 bottom
LB36  4.7uH  [IND_1D6_2SP_1D6W2L1H]  124.12 68.93 180 top
LB37  4.7uH  [IND_1D6_2SP_1D6W2L1H]  127.04 68.93 0 bottom
LB38  4.7uH  [IND_1D6_2SP_1D6W2L1H]  132.29 68.81 180 top
LB39  4.7uH  [IND_1D6_2SP_1D6W2L1H]  135.18 68.81 0 bottom
LB40  4.7uH  [IND_1D6_2SP_1D6W2L1H]  150.32 68.93 180 top
LB41  4.7uH  [IND_1D6_2SP_1D6W2L1H]  153.21 68.93 0 bottom
LB42  4.7uH  [IND_1D6_2SP_1D6W2L1H]  162.89 68.93 180 top
LB43  4.7uH  [IND_1D6_2SP_1D6W2L1H]  165.75 68.93 0 bottom
LB44  4.7uH  [IND_1D6_2SP_1D6W2L1H]  175.43 68.93 180 top
LB45  4.7uH  [IND_1D6_2SP_1D6W2L1H]  178.35 68.93 0 bottom
LB46  4.7uH  [IND_1D6_2SP_1D6W2L1H]  188.07 68.93 180 top
LB47  4.7uH  [IND_1D6_2SP_1D6W2L1H]  190.99 68.93 0 bottom
LB48  4.7uH  [IND_1D6_2SP_1D6W2L1H]  30.63 68.93 180 top
LB49  4.7uH  [IND_1D6_2SP_1D6W2L1H]  33.55 68.93 0 bottom
LB50  4.7uH  [IND_1D6_2SP_1D6W2L1H]  43.15 68.93 180 top
LB51  4.7uH  [IND_1D6_2SP_1D6W2L1H]  46.06 68.93 180 top
LB52  4.7uH  [IND_1D6_2SP_1D6W2L1H]  58.63 68.93 180 top
LB53  4.7uH  [IND_1D6_2SP_1D6W2L1H]  55.72 68.93 180 top
LB57  100MHz/3A/220mohm  [LC0603]  220.07 110.81 90 top
LB58  ESD_1  [LC0603]  239.31 76.87 0 bottom
LB59  ESD_1  [LC0603]  240.83 76.87 0 bottom
LB60  ESD_1  [LC0603]  243.12 76.87 0 bottom
LB61  ESD_1  [LC0603]  244.64 76.87 0 bottom
LB62  1uH/1.6A/60mohm  [IND_2D_2SP_2W2D5L1D2H_MAGLAYERS]  199.74 78.97 0 top
LB63  1uH/1.6A/60mohm  [IND_2D_2SP_2W2D5L1D2H_MAGLAYERS]  204.92 79.83 90 top
LB64  1uH/1.6A/60mohm  [IND_2D_2SP_2W2D5L1D2H_MAGLAYERS]  207.97 79.81 90 top
LB65  100MHZ  [LC0603]  250.03 154.02 90 top
LB66  100MHZ  [LC0603]  250.03 155.55 90 top
LB67  1uH/1.6A/60mohm  [IND_2D_2SP_2W2D5L1D2H_MAGLAYERS]  211.07 79.78 90 top
LB68  1uH/1.6A/60mohm  [IND_2D_2SP_2W2D5L1D2H_MAGLAYERS]  214.53 79.79 90 top
LB69  1uH/1.6A/60mohm  [IND_2D_2SP_2W2D5L1D2H_MAGLAYERS]  210.62 79.75 90 bottom
LB70  100MHZ  [LC0603]  250.03 152.37 90 top
LB71  100MHZ  [LC0603]  249.9 150.85 90 top
LB73  ESD_1  [LC0603]  256.95 32.01 0 bottom
LB74  ESD_1  [LC0603]  260.81 31.96 0 bottom
LB75  ESD_1  [LC0603]  256.95 32.01 180 top
LB76  ESD_1  [LC0603]  260.81 31.96 180 top
LB77  ESD_1  [LC0603]  258.92 32 0 bottom
LB78  ESD_1  [LC0603]  258.92 32 180 top
LB79  100MHz/5A/10mohm  [LC0603]  89.15 28.2 270 bottom
LB80  ESD_1  [LC0603]  88 22.74 270 bottom
LB81  ESD_1  [LC0603]  91.05 22.74 90 bottom
LB82  ESD_1  [LC0603]  92.83 20.32 180 bottom
LB83  100MHz/5A/10mohm  [LC0603]  85.59 20.2 0 bottom
LB84  ESD_1  [LC0603]  87.12 20.2 180 bottom
LB85  100MHz/5A/10mohm  [LC0603]  100.52 24.6 90 bottom
LB89  100MHz/3A/220mohm  [LC0603]  220.02 133.05 90 top
LB90  100MHz/3A/220mohm  [LC0603]  239.3 134.89 270 top
LB91  100MHz/3A/220mohm  [LC0603]  216.52 127.18 90 top
LB92  100MHz/3A/220mohm  [LC0603]  219.96 125.67 90 top
LB93  1uH/1.6A/60mohm  [IND_2D_2SP_2W2D5L1D2H_MAGLAYERS]  18.44 53.46 270 bottom
LB94  1uH/1.6A/60mohm  [IND_2D_2SP_2W2D5L1D2H_MAGLAYERS]  14.58 44.64 270 bottom
LB95  1uH/1.6A/60mohm  [IND_2D_2SP_2W2D5L1D2H_MAGLAYERS]  11.27 47.8 270 bottom
LB96  ESD_1  [LC0603]  224.78 35.17 270 bottom
LB97  ESD_1  [LC0603]  227.85 35.17 90 bottom
LB98  ESD_1  [LC0603]  227.85 35.17 270 top
LB99  ESD_1  [LC0603]  224.78 35.17 90 top
LB100  ESD_1  [LC0603]  213.13 15.07 180 bottom
LB101  ESD_1  [LC0603]  213.13 12.1 0 bottom
LB102  ESD_1  [LC0603]  213.13 23.46 180 bottom
LB103  ESD_1  [LC0603]  213.13 20.49 0 bottom
LB104  100MHz/10A/1m ohm  [LC3312_1]  82.45 238.23 270 bottom
LB105  100MHz/10A/1m ohm  [LC3312_1]  81.47 228.09 270 bottom
LB106  100MHz/10A/1m ohm  [LC3312_1]  113.6 207.97 90 bottom
LB107  100MHz/10A/1m ohm  [LC3312_1]  81.09 206.64 270 bottom
LB109  100MHz/10A/1m ohm  [LC3312_1]  81.85 221.27 270 bottom
LB110  100MHz/1A/10mohm  [LC0402]  145.25 187.11 0 top
LB113  100MHz/1A/10mohm  [LC0402]  144.62 171.42 0 bottom
LB114  100MHz/1A/10mohm  [LC0402]  43.76 205.12 90 top
LB115  100MHz/1A/10mohm  [LC0402]  108.04 176.69 270 top
LB116  100MHz/1A/10mohm  [LC0402]  141.71 164.13 180 top
LED1  LED3_7  [LED_1D6XD9_4SP_1D6WL_AC]  4.35 61.91 270 top
LED2  LED3_7  [LED_1D6XD9_4SP_1D6WL_AC]  10.53 61.91 270 top
LED3  LED3_7  [LED_1D6XD9_4SP_1D6WL_AC]  13.93 61.91 270 top
LED4  LED3_7  [LED_1D6XD9_4SP_1D6WL_AC]  20.1 61.91 270 top
LED5  SML-LX0404SIUPGUSB  [LED_D85_4SP_1WLD25H]  201.14 60.44 270 top
LED6  SML-LX0404SIUPGUSB  [LED_D85_4SP_1WLD25H]  218.1 60.44 270 top
LED7  SML-LX0404SIUPGUSB  [LED_D85_4SP_1WLD25H]  218.1 50.23 270 top
LED8  SML-LX0404SIUPGUSB  [LED_D85_4SP_1WLD25H]  201.14 50.23 0 top
LED9  LED2_1  [LED_1D2XD7_4SP_1D6WD8L_1]  26.81 54.1 90 top
LED10  LED2_1  [LED_1D2XD7_4SP_1D6WD8L_1]  37.61 50.1 90 top
LED11  LED2_1  [LED_1D2XD7_4SP_1D6WD8L_1]  41.06 54.1 90 top
LED12  LED2_1  [LED_1D2XD7_4SP_1D6WD8L_1]  51.86 50.1 90 top
LED13  LED2_1  [LED_1D2XD7_4SP_1D6WD8L]  55.31 54.1 90 top
LED14  LED2_1  [LED_1D2XD7_4SP_1D6WD8L]  66.11 50.1 90 top
LED15  LED2_1  [LED_1D2XD7_4SP_1D6WD8L]  69.56 54.1 90 top
LED16  LED2_1  [LED_1D2XD7_4SP_1D6WD8L]  80.36 50.1 90 top
LED17  LED2_1  [LED_1D2XD7_4SP_1D6WD8L]  83.81 54.1 90 top
LED18  LED2_1  [LED_1D2XD7_4SP_1D6WD8L]  94.61 50.1 90 top
LED19  LED2_1  [LED_1D2XD7_4SP_1D6WD8L]  98.06 54.1 90 top
LED20  LED2_1  [LED_1D2XD7_4SP_1D6WD8L]  108.86 50.1 90 top
LED21  LED2_1  [LED_1D2XD7_4SP_1D6WD8L]  114.36 54.1 90 top
LED22  LED2_1  [LED_1D2XD7_4SP_1D6WD8L]  125.16 50.1 90 top
LED23  LED2_1  [LED_1D2XD7_4SP_1D6WD8L]  128.61 54.1 90 top
LED24  LED2_1  [LED_1D2XD7_4SP_1D6WD8L]  139.41 50.1 90 top
LED25  LED2_1  [LED_1D2XD7_4SP_1D6WD8L]  142.86 54.1 90 top
LED26  LED2_1  [LED_1D2XD7_4SP_1D6WD8L]  153.66 50.1 90 top
LED27  LED2_1  [LED_1D2XD7_4SP_1D6WD8L]  157.11 54.1 90 top
LED28  LED2_1  [LED_1D2XD7_4SP_1D6WD8L]  167.91 50.1 90 top
LED29  LED2_1  [LED_1D2XD7_4SP_1D6WD8L]  171.36 54.1 90 top
LED30  LED2_1  [LED_1D2XD7_4SP_1D6WD8L]  182.16 54.1 90 top
LED31  LED2_1  [LED_1D2XD7_4SP_1D6WD8L]  185.61 54.1 90 top
LED32  LED2_1  [LED_1D2XD7_4SP_1D6WD8L]  196.41 50.1 90 top
LED33  LED1_1  [LED_1D5_2SP_D8W1D6LD6H_AC]  191.86 238.24 270 top
LED34  LED2_1  [LED_1D2XD7_4SP_1D6WD8L_1]  26.81 50.1 90 top
LED35  LED2_1  [LED_1D2XD7_4SP_1D6WD8L_1]  37.61 54.1 90 top
LED36  LED2_1  [LED_1D2XD7_4SP_1D6WD8L_1]  41.06 50.1 90 top
LED37  LED2_1  [LED_1D2XD7_4SP_1D6WD8L_1]  51.86 54.1 90 top
LED38  LED2_1  [LED_1D2XD7_4SP_1D6WD8L]  55.31 50.1 90 top
LED39  LED2_1  [LED_1D2XD7_4SP_1D6WD8L]  66.11 54.1 90 top
LED40  LED2_1  [LED_1D2XD7_4SP_1D6WD8L]  69.56 50.1 90 top
LED41  LED2_1  [LED_1D2XD7_4SP_1D6WD8L]  80.36 54.1 90 top
LED42  LED2_1  [LED_1D2XD7_4SP_1D6WD8L]  83.81 50.1 90 top
LED43  LED2_1  [LED_1D2XD7_4SP_1D6WD8L]  94.61 54.1 90 top
LED44  LED2_1  [LED_1D2XD7_4SP_1D6WD8L]  98.06 50.1 90 top
LED45  LED2_1  [LED_1D2XD7_4SP_1D6WD8L]  108.86 54.1 90 top
LED46  LED2_1  [LED_1D2XD7_4SP_1D6WD8L]  114.36 50.1 90 top
LED47  LED2_1  [LED_1D2XD7_4SP_1D6WD8L]  125.16 54.1 90 top
LED48  LED2_1  [LED_1D2XD7_4SP_1D6WD8L]  128.61 50.1 90 top
LED49  LED2_1  [LED_1D2XD7_4SP_1D6WD8L]  139.41 54.1 90 top
LED50  LED2_1  [LED_1D2XD7_4SP_1D6WD8L]  142.86 50.1 90 top
LED51  LED2_1  [LED_1D2XD7_4SP_1D6WD8L]  153.66 54.1 90 top
LED52  LED2_1  [LED_1D2XD7_4SP_1D6WD8L]  157.11 50.1 90 top
LED53  LED2_1  [LED_1D2XD7_4SP_1D6WD8L]  167.91 54.1 90 top
LED54  LED2_1  [LED_1D2XD7_4SP_1D6WD8L]  171.36 50.1 90 top
LED55  LED2_1  [LED_1D2XD7_4SP_1D6WD8L]  182.16 50.1 90 top
LED56  LED2_1  [LED_1D2XD7_4SP_1D6WD8L]  185.61 50.1 90 top
LED57  LED2_1  [LED_1D2XD7_4SP_1D6WD8L]  196.41 54.1 90 top
LEDB3  LED2_3_1  [LED_3D_3SP_3W2L_AC1C2]  248.17 4.95 0 bottom
LEDB4  LED2_3_1  [LED_3D_3SP_3W2L_AC1C2]  241.17 4.95 0 bottom
LEDB5  LED1_1  [LED_2D8_2SP_3W2L1H_AC]  227.2 4.95 0 bottom
LEDB6  LED1_1  [LED_2D8_2SP_3W2L1H_AC]  234.2 4.95 0 bottom
LEDB7  LED2_3_1  [LED_3D_3SP_3W2L_AC1C2]  44.2 4.95 0 bottom
LEDB8  LED2_3_1  [LED_3D_3SP_3W2L_AC1C2]  65.14 4.95 0 bottom
LEDB9  LED2_3_1  [LED_3D_3SP_3W2L_AC1C2]  51.17 4.95 0 bottom
LEDB10  LED2_3_1  [LED_3D_3SP_3W2L_AC1C2]  58.17 4.95 0 bottom
LEDB11  LED1_1  [LED_3D_2SP_1W3L_AC]  37.2 4.95 0 bottom
LEDB12  LED1_1  [LED_2D8_2SP_3W2L1H_AC]  157.46 259.25 0 top
LEDB13  LED1_1  [LED_2D8_2SP_3W2L1H_AC]  262.14 4.95 0 bottom
LEDB14  LED1_1  [LED_2D8_2SP_3W2L1H_AC]  255.14 4.95 0 bottom
LEDB15  LED2_3  [LED_3D5_3SP_1W3L_A_C1_C2]  72.14 4.95 0 bottom
NOREF  -  []  129.84 227.5 0 top
NOREF#2  -  []  264.65 178.7 0 top
NOREF#3  -  []  264.65 98.7 0 top
NOREF#4  -  []  264.95 52.61 0 top
NOREF#5  -  []  246.84 140.5 0 top
NOREF#6  -  []  90.07 249.68 0 top
NOREF#7  -  []  129.84 140.5 0 top
NOREF#8  -  []  512.98 -62.89 0 top
NOREF#9  -  []  202.17 127.34 270 top
NOREF#10  -  []  91.46 145.41 0 top
NOREF#11  -  []  7.2 256.7 0 top
NOREF#12  -  []  246.84 140.5 0 top
NOREF#13  -  []  91.46 145.41 0 top
NOREF#14  -  []  144.65 258.7 0 top
NOREF#15  -  []  5.87 182.28 0 top
NOREF#16  -  []  163.36 207.2 0 top
NOREF#17  -  []  216.84 227.5 0 top
NOREF#18  -  []  30.3 216.7 0 top
NOREF#19  -  []  98.58 71.61 0 top
NOREF#20  -  []  129.84 227.5 0 top
NOREF#21  -  []  200.12 86.07 0 top
NOREF#22  -  []  191.36 163.2 0 top
NOREF#23  -  [unnamed#2]  20.62 256.57 0 top
NOREF#24  -  []  16.6 105.64 90 top
NOREF#25  -  []  25.07 176.65 90 top
NOREF#26  -  []  216.84 227.5 0 top
NOREF#27  -  []  200.12 86.07 0 top
NOREF#28  -  []  200.12 112.11 0 top
NOREF#29  -  []  139.67 86.07 0 top
NOREF#30  -  []  246.84 140.5 0 top
NOREF#31  -  []  12.94 102.84 90 top
NOREF#32  -  []  11.6 111.35 90 top
NOREF#33  -  []  191.36 163.2 0 top
NOREF#34  -  []  5.87 182.28 0 top
NOREF#35  -  []  0 0 0 top
NOREF#36  -  []  246.84 227.5 0 top
NOREF#37  -  []  246.84 227.5 0 top
NOREF#38  -  []  40.72 65.49 0 top
NOREF#39  -  []  90.07 249.68 0 top
NOREF#40  -  []  98.58 71.61 0 top
NOREF#41  -  []  14.85 107.92 90 top
NOREF#42  -  []  264.65 98.7 0 top
NOREF#43  -  []  264.65 178.7 0 top
NOREF#44  -  []  7.2 256.7 0 top
NOREF#45  -  [unnamed#2]  263.9 42.94 0 top
NOREF#46  -  []  7.2 72.2 0 top
NOREF#47  -  []  205.84 140.5 0 top
NOREF#48  -  []  264.65 258.7 0 top
NOREF#49  -  []  139.67 112.11 0 top
NOREF#50  -  []  139.67 112.11 0 top
NOREF#51  -  []  73.5 161.47 90 top
NOREF#52  -  []  16.27 102.84 90 top
NOREF#53  -  []  73.47 164.23 90 top
NOREF#54  -  []  7.2 72.2 0 top
NOREF#55  -  []  144.65 258.7 0 top
NOREF#56  -  []  264.65 258.7 0 top
NOREF#57  -  [unnamed#2]  9.94 175.44 0 top
NOREF#58  -  []  -23.33 243.08 0 top
NOREF#59  -  []  12.94 105.64 90 top
NOREF#60  -  []  129.84 140.5 0 top
NOREF#61  -  []  139.67 86.07 0 top
NOREF#62  -  []  264.95 52.61 0 top
NOREF#63  -  []  200.12 112.11 0 top
NOREF#64  -  []  30.3 216.7 0 top
NOREF#65  -  []  163.36 207.2 0 top
NOREF#66  -  [unnamed#2]  262.94 245.83 0 top
NOREF#67  -  [unnamed#2]  51.11 255.69 180 bottom
NOREF#68  -  [unnamed#2]  253.35 257 180 bottom
NOREF#69  -  []  323.18 158.06 270 bottom
NOREF#70  -  [unnamed#2]  264.7 29.46 180 bottom
NUT1  NUT_1  [NUT_295C166D_PTH]  90.07 249.68 0 top
OCXO1  25MHz (STP 3377 LF)  [OCXO_8D9X23D4_7SP_22W25D4L]  256.23 120.61 180 top
OCXO2  25MHz  [OSC_2D54X7D5_6SP_14D6W9D7L6D2H]  256.21 120.63 180 top
OSC1  25MHz  [OSC_1D6X2D12_4SP_2D5W3D2L1DH]  85.55 214 0 top
OSC2  2.048MHz  [OSC_2D1X1D6_4SP_2D5WX3D2L]  200.18 232.57 270 top
OSC3  25MHz  [OSC_1D6X2D12_4SP_2D5W3D2L1DH]  183.15 189.96 0 top
OSC5  25MHz  [OSC_1D6X2D12_4SP_2D5W3D2L1DH]  10.46 154.98 270 top
OSC6  12MHz+-10ppm  [OSC_1D6X2D12_4SP_2D5W3D2LD75H]  228.7 181.68 0 top
OSC7  114.285MHz  [OSC_4DX5D08_4SP_7W5L]  148.81 165.19 0 top
OSCB1  25MHz+/-10ppm  [OSC_1D6X2D12_4SP_2D5W3D2LD75H]  83.93 181.03 0 top
P1  EP4CGX30CF23I7N  [BGA_1D_20C_484SP_23WL2D44H]  105.29 220.46 90 top
PTC1  3A  [PTC_2D8_2SP_3D2W1D65L]  70.45 72.49 180 top
PTC2  3A  [PTC_2D8_2SP_3D2W1D65L]  82.96 72.49 180 top
PTC3  3A  [PTC_2D8_2SP_3D2W1D65L]  113.77 72.49 180 top
PTC4  3A  [PTC_2D8_2SP_3D2W1D65L]  126.35 72.49 180 top
PTC5  3A  [PTC_2D8_2SP_3D2W1D65L]  134.48 72.36 180 top
PTC6  3A  [PTC_2D8_2SP_3D2W1D65L]  152.51 72.49 180 top
PTC7  3A  [PTC_2D8_2SP_3D2W1D65L]  165.02 72.49 180 top
PTC8  3A  [PTC_2D8_2SP_3D2W1D65L]  177.65 72.49 180 top
PTC9  3A  [PTC_2D8_2SP_3D2W1D65L]  190.29 72.49 180 top
PTC10  3A  [PTC_2D8_2SP_3D2W1D65L]  32.85 72.49 180 top
PTC11  3A  [PTC_2D8_2SP_3D2W1D65L]  45.36 72.49 180 top
PTC12  3A  [PTC_2D8_2SP_3D2W1D65L]  57.94 72.49 180 top
PTCB1  3A  [PTC_2D8_2SP_3D2W1D65L]  208.91 84.35 90 top
PTCB2  3A  [PTC_2D8_2SP_3D2W1D65L]  211.34 84.35 90 top
PTCB3  3A  [PTC_2D8_2SP_3D2W1D65L]  17.36 44.85 90 bottom
Q1  N-CH  [SOT23_D95X2D2_3SP_2D92W1D3L_GSD]  131.99 216.41 270 top
Q2  N-CH  [SOT23_D95X2D2_3SP_2D92W1D3L_GSD]  83.02 233.72 90 top
Q3  N-CH  [SOT23_D95X2D2_3SP_2D92W1D3L_GSD]  132.05 219.9 270 top
Q4  N-CH  [SOT23_D95X2D2_3SP_2D92W1D3L_GSD]  132.06 212.91 270 top
Q5  N-CH  [SOT23_D95X2D2_3SP_2D92W1D3L_GSD]  83.02 229.97 90 top
QB2  N-CH  [SOT23_D95X2D2_3SP_2D92W1D3L_GSD]  143.54 232.06 270 top
QB4  N-CH  [SOT23_D95X2D2_3SP_2D92W1D3L_GSD]  86.98 204.46 90 top
QB5  N-CH  [SOT23_D95X2D2_3SP_2D92W1D3L_GSD]  81.05 224.51 90 top
QB6  N-CH  [SOT23_D95X2D2_3SP_2D92W1D3L_GSD]  81.18 220.83 90 top
QB7  N-CH  [SOT23_D95X2D2_3SP_2D92W1D3L_GSD]  127.27 204.8 270 top
QB8  N-CH  [SOT23_D95X2D2_3SP_2D92W1D3L_GSD]  143.48 228.45 270 top
QB9  N-CH  [SOT23_D95X2D2_3SP_2D92W1D3L_GSD]  143.48 235.81 270 top
R1  4.02K  [RC0603]  228.15 232.74 90 top
R2  @0  [RC0402]  226.51 229.48 0 top
R3  0  [RC0402]  228.75 229.48 180 top
R4  8.06K  [RC0402]  231.84 232.7 0 top
R5  8.06K  [RC0402]  233.11 232.7 0 top
R6  4.7K  [RC0402]  234.38 232.7 0 top
R7  4.7K  [RC0402]  235.65 232.7 0 top
R14  4.02K  [RC0603]  230.07 229.88 180 top
R15  4.02K  [RC0603]  231.67 229.83 180 top
R16  4.02K  [RC0603]  233.11 229.88 180 top
R18  1K  [RC0402]  234.51 229.53 180 top
R19  1K  [RC0402]  235.65 229.53 180 top
R25  0  [RC0402]  227.61 229.48 0 top
R30  4.02K  [RC0603]  238.58 228.38 270 top
R39  @2.21K  [RC0402]  222.98 224.76 90 top
R40  @2.21K  [RC0402]  226.46 227.17 0 top
R41  4.02K  [RC0603]  238.58 226.86 90 top
R45  10K  [RC0402]  61.93 184.84 180 top
R48  0  [RC0603]  62.87 192.44 0 top
R49  10Kohm  [RC0603]  61.89 182.39 180 top
R52  10K  [RC0402]  222.68 222.64 90 top
R53  0  [RC0402]  240.94 223.93 90 top
R54  4.7K  [RC0402]  82.82 213.51 180 top
R55  0  [RC0603]  64.34 192.46 0 top
R56  31.6K  [RC0402]  238.21 223.14 270 top
R57  31.6K  [RC0402]  238.21 222.12 270 top
R58  100K  [RC0402]  65.23 190.3 270 top
R59  0  [RC0402]  89.69 220.89 270 top
R60  0  [RC0402]  89.7 213.21 90 bottom
R61  0  [RC0402]  104.13 236.39 0 top
R62  @0  [RC0402]  89.68 208.1 270 top
R64  0  [RC0402]  65.61 191.83 180 top
R65  10K  [RC0402]  222.66 221.54 90 top
R66  @0  [RC0402]  66.62 191.83 180 top
R67  24.9K  [RC0402]  91.09 204.39 180 top
R68  0  [RC0402]  240.94 222.4 90 top
R69  @0  [RC0402]  88.18 214.79 0 top
R70  1K  [RC0402]  67.13 190.3 270 top
R71  @10K  [RC0402]  222.66 220.45 90 top
R72  0  [RC0402]  92.1 204.39 180 top
R73  @4.7K  [RC0402]  143.21 245.12 90 top
R74  0  [RC0402]  184.96 201.25 270 top
R75  0  [RC0402]  121.25 234.6 90 top
R76  33  [RC0402]  89.19 214.77 0 top
R77  0  [RC0402]  89.69 211.17 270 top
R78  0  [RC0402]  89.69 212.19 90 top
R79  0  [RC0402]  89.69 210.16 270 top
R80  4.02K  [RC0603]  241.45 219.67 90 top
R81  4.02K  [RC0603]  241.45 221.13 270 top
R82  0  [RC0402]  105.15 236.4 180 top
R83  0  [RC0402]  103.12 236.38 180 top
R84  0  [RC0402]  106.16 236.38 180 top
R85  0  [RC0402]  106.62 236.39 0 bottom
R86  @0  [RC0402]  222.65 219.37 90 top
R87  4.7K  [RC0402]  108.2 236.38 180 top
R88  4.7K  [RC0402]  143.21 244.09 90 top
R89  0  [RC0402]  118.3 236.36 180 top
R94  33  [RC0402]  161.13 176.88 270 top
R95  0  [RC0402]  240.73 218.22 90 top
R96  @4.7K  [RC0402]  153.88 243.32 270 top
R97  4.7K  [RC0402]  222.68 218.3 90 top
R98  33  [RC0402]  107.18 236.38 180 top
R99  4.7K  [RC0402]  143.21 243.07 90 top
R100  24.9K  [RC0402]  86.45 221.52 270 top
R106  4.7K  [RC0402]  153.88 242.31 90 top
R107  4.7K  [RC0402]  222.68 216.12 90 top
R108  4.02K  [RC0603]  240.99 216.95 90 top
R109  4.02K  [RC0603]  241 215.48 270 top
R110  33  [RC0402]  111.22 236.36 180 top
R111  @4.7K  [RC0402]  143.21 242.05 90 top
R112  0 ohm  [RC0402]  89.69 219.87 90 top
R116  4.7K  [RC0402]  112.23 236.36 180 top
R117  @4.7K  [RC0402]  143.21 241.04 90 top
R118  0  [RC0402]  240.56 214.28 90 top
R119  0  [RC0402]  222.68 215.08 270 top
R120  33  [RC0402]  119.32 236.36 180 top
R121  4.7K  [RC0402]  143.21 240.02 90 top
R132  0  [RC0402]  121.51 204.3 0 top
R134  0  [RC0402]  222.68 214.01 270 top
R137  24.9K  [RC0402]  122.52 204.3 0 top
R138  @0  [RC0402]  117.31 236.38 180 top
R139  24.9K  [RC0402]  84.1 219.43 180 top
R140  40.2  [RC0402]  21.91 175.64 0 top
R141  40.2  [RC0402]  22.85 175.64 0 top
R142  40.2  [RC0402]  23.99 175.64 0 top
R143  40.2  [RC0402]  25.01 175.64 0 top
R144  40.2  [RC0402]  27.04 175.64 0 top
R145  40.2  [RC0402]  28.06 175.64 0 top
R146  40.2  [RC0402]  29.18 175.61 0 top
R147  40.2  [RC0402]  55.34 175.49 0 top
R148  40.2  [RC0402]  60.42 175.49 0 top
R149  40.2  [RC0402]  61.43 175.49 0 top
R150  40.2  [RC0402]  62.45 175.49 0 top
R151  40.2  [RC0402]  63.47 175.49 0 top
R152  40.2  [RC0402]  64.48 175.49 0 top
R153  40.2  [RC0402]  65.5 175.49 0 top
R154  40.2  [RC0402]  66.51 175.49 0 top
R155  40.2  [RC0402]  67.53 175.49 0 top
R156  40.2  [RC0402]  68.55 175.49 0 top
R157  40.2  [RC0402]  69.56 175.49 0 top
R158  40.2  [RC0402]  70.58 175.49 0 top
R161  0  [RC0402]  238.51 212 0 top
R162  0  [RC0402]  89.7 209.14 270 top
R163  40.2  [RC0402]  26 175.23 0 top
R165  0  [RC0402]  226.69 212.13 180 top
R166  1K  [RC0402]  227.78 212.13 180 top
R167  10K  [RC0402]  228.8 212.13 180 top
R168  @4.7K  [RC0402]  160.84 234.38 180 top
R169  4.7K  [RC0402]  160.84 231.84 180 top
R178  33  [RC0402]  184.25 193.86 90 top
R179  40.2  [RC0402]  77.94 174.47 90 top
R180  33  [RC0402]  161.76 216.89 0 top
R181  0  [RC0402]  89.69 226.98 270 top
R182  10K  [RC0402]  174.46 220.19 270 top
R183  33  [RC0402]  121.25 232.57 90 top
R184  4.7K  [RC0402]  159.83 234.38 180 top
R185  @4.7K  [RC0402]  159.83 231.84 180 top
R186  @0  [RC0402]  184.25 192.86 90 top
R187  40.2  [RC0402]  77.94 173.45 90 top
R188  0  [RC0402]  89.69 218.86 90 top
R189  4.7K  [RC0402]  159.73 214.35 0 top
R190  @4.7K  [RC0402]  159.73 216.89 180 top
R191  0  [RC0402]  89.69 221.9 270 top
R192  @0  [RC0402]  198.34 228.95 270 top
R193  33  [RC0402]  121.25 231.56 90 top
R194  0  [RC0402]  227.25 209.78 180 top
R195  4.02K  [RC0603]  237.05 210.1 90 top
R196  0  [RC0402]  228.29 209.78 0 top
R197  40.2  [RC0402]  77.94 172.44 90 top
R204  0  [RC0402]  198.34 229.97 270 top
R205  0  [RC0402]  91.89 236.38 180 top
R206  0  [RC0402]  230.57 208.7 270 top
